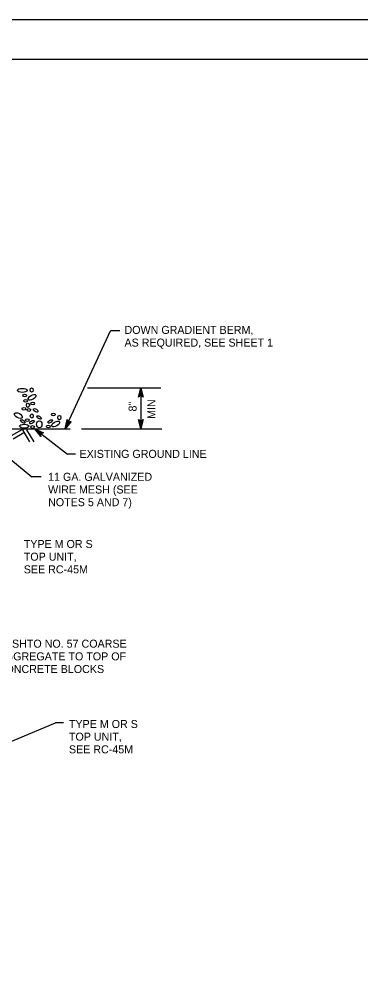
# Model space of a CAD drawing. Extents: x 636183 to 639890, y 299162 to 300538.
# Drawn here: x 637548.8 to 637676.7, y 300175.3 to 300538.4 of the extents above; entities that cross this region are included whole.
import ezdxf

# ---------------------------------------------------------------- set-up
doc = ezdxf.new("R2010")
doc.units = 0
for name, color, linetype in [('1', 7, 'Continuous'), ('Default', 7, 'Continuous'), ('PLT-BNDY', 7, 'Continuous')]:
    doc.layers.add(name, color=color, linetype=linetype)

msp = doc.modelspace()

# ---------------------------------------------------------------- linework, layer by layer
at = {"layer": '1'}
msp.add_lwpolyline([(638128.91, 299959.45), (638128.91, 300523.45), (637342.91, 300523.45), (637342.91, 299959.45), (638128.91, 299959.45), (638128.91, 299985.81), (637928.91, 299985.81), (637928.91, 300050.49), (638128.91, 300050.49), (638128.91, 300079.45), (637928.91, 300079.45), (637928.91, 299959.45), (638007.72, 299959.45), (638007.72, 299985.81), (638007.72, 299959.45), (638084.72, 299959.45), (638084.72, 299985.81), (638084.72, 299973.49), (638128.91, 299973.49)], dxfattribs=at)
at = {"layer": 'Default'}
for p, q in [((637565.91, 300384.99), (637582.92, 300421.77)), ((637586.42, 300421.77), (637582.92, 300421.77)), ((637574.27, 300400.34), (637601.79, 300400.34)), ((637525.6, 300389.73), (637553.49, 300367.09)), ((637525.55, 300384.99), (637567.76, 300384.99)), ((637549.65, 300384.72), (637545.71, 300382.38)), ((637549.92, 300384.7), (637552.57, 300380.22)), ((637551.49, 300384.7), (637554.14, 300380.22)), ((637554.54, 300384.99), (637566.81, 300375.53)), ((637550.37, 300383.51), (637546.43, 300381.17)), ((637569.81, 300375.53), (637566.81, 300375.53)), ((637556.98, 300367.09), (637553.49, 300367.09)), ((637516.68, 300255.74), (637562.35, 300274.87)), ((637565.35, 300274.87), (637562.35, 300274.87))]:
    msp.add_line(p, q, dxfattribs=at)
for points in [[(637593.61, 300397.11), (637593.38, 300396.84), (637594.25, 300400.34), (637593.61, 300397.11), (637593.98, 300397.31), (637594.25, 300400.34), (637594.5, 300397.31), (637594.88, 300397.13), (637594.25, 300400.34), (637595.13, 300396.85), (637594.88, 300397.13)], [(637594.25, 300400.34), (637594.25, 300384.99)], [(637567.9, 300387.61), (637568.22, 300387.76), (637565.91, 300384.99), (637567.9, 300387.61), (637567.48, 300387.6), (637565.91, 300384.99), (637567, 300387.82), (637566.74, 300388.15), (637565.91, 300384.99), (637566.64, 300388.52), (637566.74, 300388.15)], [(637594.88, 300388.22), (637595.11, 300388.49), (637594.25, 300384.99), (637594.88, 300388.22), (637594.51, 300388.02), (637594.25, 300384.99), (637593.99, 300388.02), (637593.61, 300388.2), (637594.25, 300384.99), (637593.36, 300388.48), (637593.61, 300388.2)], [(637556.7, 300382.5), (637556.78, 300382.16), (637554.54, 300384.99), (637556.7, 300382.5), (637556.78, 300382.91), (637554.54, 300384.99), (637557.09, 300383.33), (637557.47, 300383.52), (637554.54, 300384.99), (637557.85, 300383.54), (637557.47, 300383.52)], [(637572.11, 300384.99), (637602.15, 300384.99), (637602.15, 300384.99)]]:
    msp.add_lwpolyline(points, dxfattribs=at)
for centre, major_axis, ratio in [((637549.84, 300399.44), (1.8, 0), 0.416735), ((637553.36, 300399.58), (0, 0.816), 0.679012), ((637550.76, 300397.54), (0.693, 0), 0.736364), ((637551.08, 300395.57), (0.693, 0), 0.736364), ((637551.95, 300393.9), (0, 0.816), 0.679012), ((637553.53, 300396.85), (1.4, 0.79), 0.520021), ((637553.75, 300394.53), (0.693, 0), 0.736364), ((637548.38, 300390), (1.4, -0.79), 0.520021), ((637550.45, 300392.55), (0.693, 0), 0.736364), ((637552.34, 300392.09), (0.693, 0), 0.736364), ((637554.88, 300391.96), (-0.843, 0.513), 0.464326), ((637550.01, 300387.79), (-0.843, 0.513), 0.464326), ((637551.71, 300388.27), (0.693, 0), 0.736364), ((637553.5, 300387.58), (0.843, 0.513), 0.464326), ((637553.4, 300389.83), (0, 0.816), 0.679012), ((637556.14, 300389.3), (-0.843, 0.513), 0.464326), ((637556.22, 300386.73), (0, -1.33), 0.768555), ((637560.35, 300387.81), (0.843, 0.513), 0.464326), ((637562.38, 300386.85), (1.4, 0.79), 0.520021), ((637561.52, 300390.45), (0.693, 0), 0.736364), ((637563.75, 300389.27), (0, 0.816), 0.679012), ((637550.58, 300386.02), (1.8, 0), 0.416735), ((637553.71, 300385.72), (0.693, 0), 0.736364), ((637559.57, 300385.95), (0.693, 0), 0.736364)]:
    msp.add_ellipse(centre, major_axis=major_axis, ratio=ratio, start_param=0, end_param=6.283175, dxfattribs=at)
at = {"layer": 'PLT-BNDY'}
msp.add_lwpolyline([(637302.91, 300538.45), (638143.91, 300538.45), (638143.91, 299944.45), (637302.91, 299944.45)], close=True, dxfattribs=at)

# ---------------------------------------------------------------- texts
at = {"layer": 'Default'}
for s, p in [('DOWN GRADIENT BERM,', (637588.17, 300420.6)), ('AS REQUIRED, SEE SHEET 1', (637588.17, 300415.85)), ('EXISTING GROUND LINE', (637571.31, 300374.16)), ('11 GA. GALVANIZED', (637559.53, 300365.56)), ('WIRE MESH (SEE', (637559.53, 300360.81)), ('NOTES 5 AND 7)', (637559.53, 300356.06)), ('TYPE M OR S', (637550.41, 300340.39)), ('TOP UNIT,', (637550.41, 300335.64)), ('SEE RC-45M', (637550.41, 300330.89)), ('AASHTO NO. 57 COARSE', (637540.65, 300303.04)), ('AGGREGATE TO TOP OF', (637540.65, 300298.29)), ('CONCRETE BLOCKS', (637540.65, 300293.54)), ('TYPE M OR S', (637567.34, 300272.95)), ('TOP UNIT,', (637567.34, 300268.2)), ('SEE RC-45M', (637567.34, 300263.45))]:
    msp.add_text(s, height=2.998, dxfattribs=at).set_placement(p)
for s, p in [('8"', (637592.7, 300391.53)), ('MIN', (637599.76, 300388.75))]:
    msp.add_text(s, height=2.998, rotation=90, dxfattribs=at).set_placement(p)

doc.saveas('drawing.dxf')
